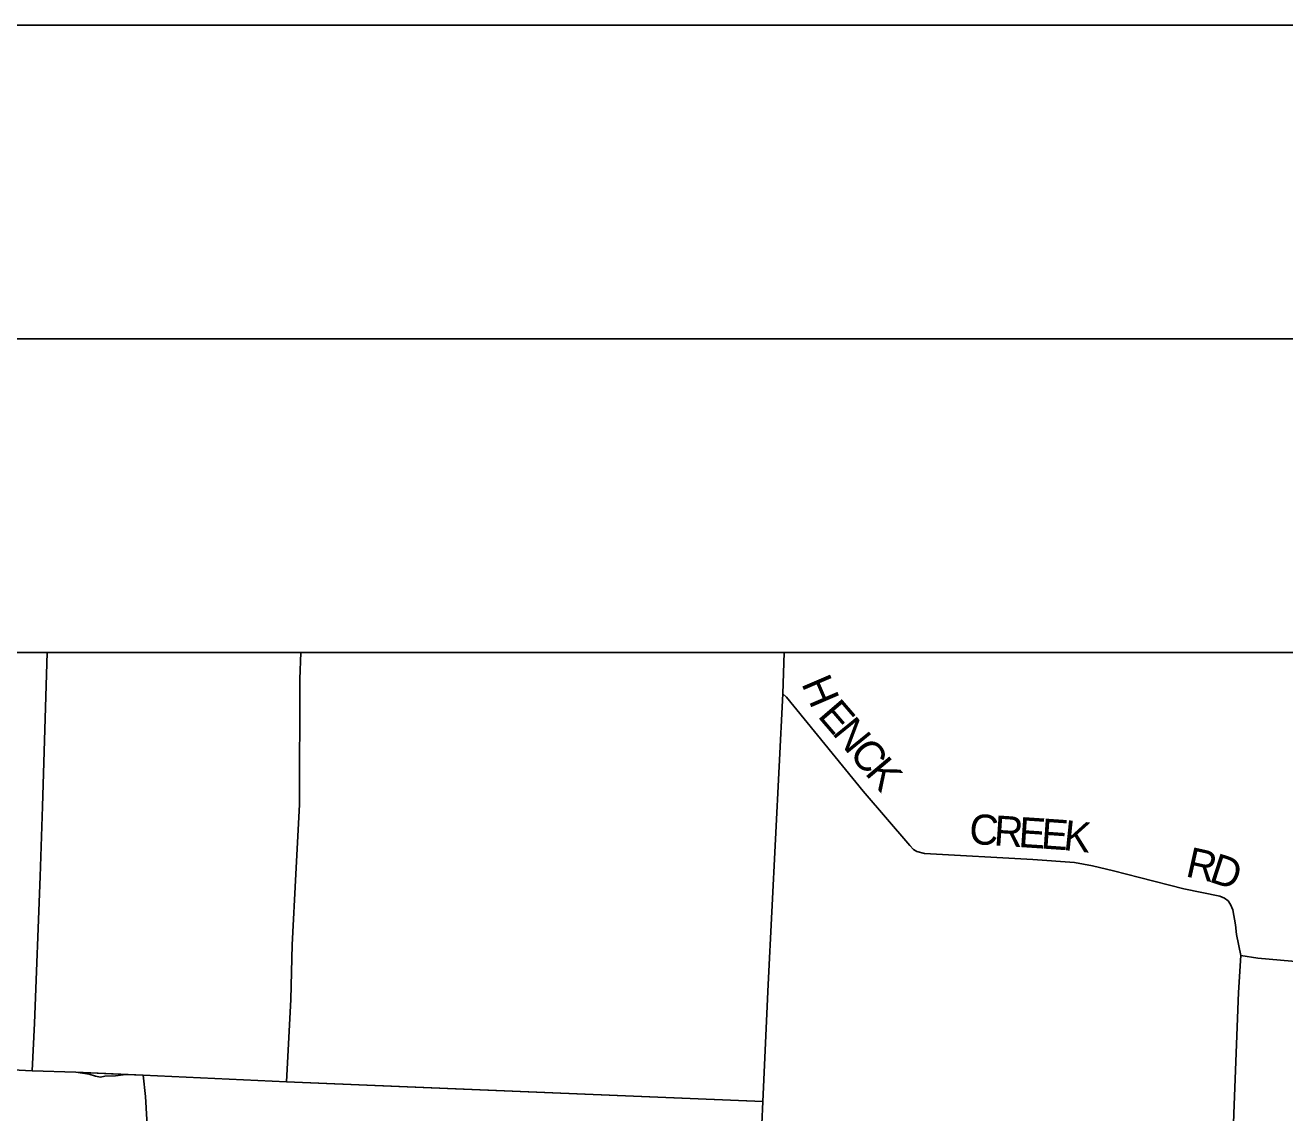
# Model space of a CAD drawing. Extents: x 41.3 to 81.6, y -19.3 to 2.7.
# Drawn here: x 46.925 to 48.932, y 1 to 2.734 of the extents above; entities that cross this region are included whole.
import ezdxf

# ---------------------------------------------------------------- set-up
doc = ezdxf.new("R2010")
doc.units = 0
for name, color, linetype in [('GM_X_County_Road', 7, 'Continuous'), ('GM_X_County_Road_Text', 7, 'Continuous'), ('GM_X_Township', 7, 'Continuous'), ('GM_X_Township_Road', 7, 'Continuous'), ('SH_Border', 7, 'Continuous'), ('SH_Cut_Line', 7, 'Continuous'), ('SH_Data', 7, 'Continuous')]:
    doc.layers.add(name, color=color, linetype=linetype)

msp = doc.modelspace()

# ---------------------------------------------------------------- linework, layer by layer
at = {"layer": 'GM_X_County_Road'}
msp.add_line((48.1343, 1.7338), (48.132, 1.668), dxfattribs=at)
for points in [[(48.132, 1.668), (48.138, 1.6627), (48.2602, 1.5126), (48.3347, 1.426), (48.3404, 1.4199), (48.3455, 1.4163), (48.358, 1.4134), (48.5305, 1.4036), (48.5967, 1.3991), (48.6255, 1.3938), (48.6591, 1.3859), (48.7003, 1.3752), (48.771, 1.3572), (48.8286, 1.3454), (48.8359, 1.3421), (48.8416, 1.3376), (48.8458, 1.3321), (48.8493, 1.3235), (48.8533, 1.2997), (48.8551, 1.284), (48.8618, 1.2505), (48.8892, 1.2463), (49.0031, 1.2362)], [(48.8494, 0.9506), (48.85, 0.9656), (48.8511, 0.999), (48.8585, 1.1918), (48.8618, 1.2505)]]:
    msp.add_lwpolyline(points, dxfattribs=at)
at = {"layer": 'GM_X_Township'}
for points in [[(43.8231, 1.2245), (45.083, 1.1614), (45.1156, 1.1595), (45.1332, 1.1586), (45.1439, 1.1572), (45.1704, 1.1555), (45.9476, 1.1106), (46.1745, 1.1003), (46.5758, 1.0845), (46.6145, 1.084), (46.6225, 1.0834), (46.6323, 1.082), (46.9356, 1.0671), (47.0053, 1.0645), (47.1126, 1.0599), (47.341, 1.0494), (48.1003, 1.0179), (48.1087, 1.2045), (48.132, 1.668), (48.1343, 1.7338), (43.8015, 1.7338)], [(46.6323, 1.082), (46.9356, 1.0671), (47.0053, 1.0645), (47.0849, 1.0611), (47.1126, 1.0599), (47.341, 1.0494), (47.5073, 1.0425), (48.1003, 1.0179), (48.0986, 0.982), (48.0693, 0.447), (48.0597, 0.2729), (48.0177, -0.5949), (47.9927, -1.1134), (47.3982, -1.085), (46.8967, -1.0581)]]:
    msp.add_lwpolyline(points, dxfattribs=at)
at = {"layer": 'GM_X_Township_Road'}
for points in [[(46.9356, 1.0671), (46.9395, 1.1427), (46.9484, 1.3768), (46.9524, 1.4881), (46.9598, 1.7338)], [(47.3641, 1.7338), (47.3621, 1.6913), (47.3617, 1.4916), (47.356, 1.3805)], [(48.132, 1.668), (48.1087, 1.2045), (48.1003, 1.0179)], [(47.356, 1.3805), (47.3502, 1.2678), (47.3478, 1.1804), (47.341, 1.0494)], [(46.6323, 1.082), (46.9356, 1.0671)], [(46.9356, 1.0671), (47.0053, 1.0645), (47.0264, 1.0613), (47.0367, 1.0585), (47.0445, 1.057), (47.0514, 1.0581), (47.0688, 1.059), (47.0849, 1.0611), (47.1126, 1.0599)], [(47.1126, 1.0599), (47.1165, 1.0262), (47.1201, 0.9615), (47.1207, 0.9307), (47.1207, 0.9142), (47.1162, 0.9002), (47.1129, 0.8939), (47.1048, 0.8873), (47.0892, 0.8736), (47.0761, 0.8591), (47.0702, 0.8533), (47.0603, 0.8394), (47.0575, 0.8328), (47.0556, 0.8247), (47.0539, 0.7966), (47.0478, 0.7858)], [(47.1126, 1.0599), (47.341, 1.0494)], [(47.341, 1.0494), (47.5073, 1.0425), (48.1003, 1.0179)], [(48.1003, 1.0179), (48.0986, 0.982)]]:
    msp.add_lwpolyline(points, dxfattribs=at)
at = {"layer": 'SH_Border'}
msp.add_lwpolyline([(42.7645, 2.2338), (74.7645, 2.2338), (74.7645, -18.7662), (42.7645, -18.7662)], close=True, dxfattribs=at)
at = {"layer": 'SH_Cut_Line'}
msp.add_lwpolyline([(41.2645, -19.2662), (75.2645, -19.2662), (75.2645, 2.7338), (41.2645, 2.7338)], close=True, dxfattribs=at)
at = {"layer": 'SH_Data'}
msp.add_line((43.2645, 1.7338), (50.2645, 1.7338), dxfattribs=at)

# ---------------------------------------------------------------- texts
at = {"layer": 'GM_X_County_Road_Text'}
for s, rotation, p in [('H', 293.1977, (48.1612, 1.6844)), ('E', 310.6715, (48.1863, 1.6321)), ('N', 309.0831, (48.2095, 1.6051)), ('C', 309.2103, (48.2362, 1.5723)), ('K', 310.1784, (48.2617, 1.541)), ('C', 356.2036, (48.4281, 1.429)), ('R', 356.1997, (48.4675, 1.4264)), ('E', 356.2055, (48.5068, 1.4238)), ('E', 356.0283, (48.5426, 1.4214)), ('K', 354.015, (48.578, 1.419)), ('R', 347.4691, (48.7724, 1.3772)), ('D', 341.7528, (48.8096, 1.369))]:
    msp.add_text(s, height=0.048, rotation=rotation, dxfattribs=at).set_placement(p)

doc.saveas('drawing.dxf')
